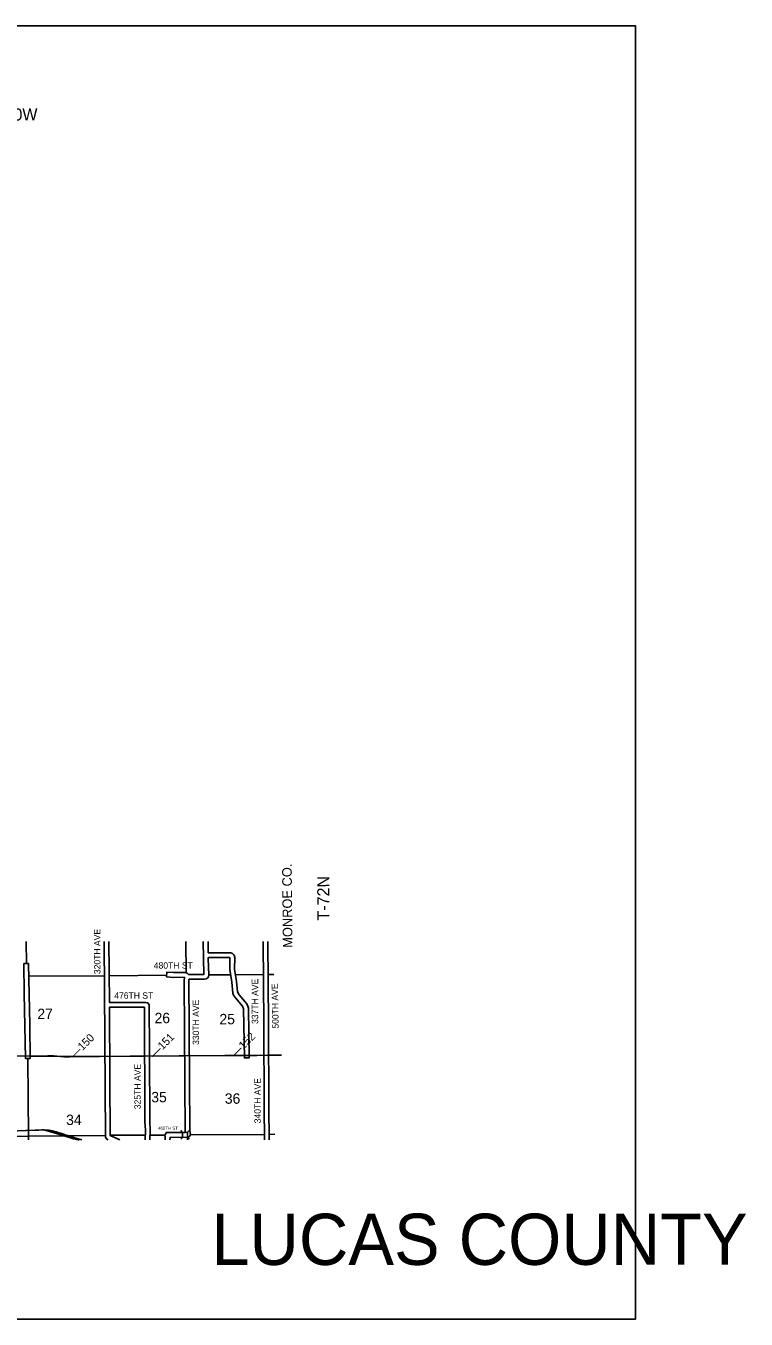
# Model space of a CAD drawing. Extents: x 10133 to 81668, y 5524 to 11018.
# Drawn here: x 19515 to 20640, y 7924 to 9944 of the extents above; entities that cross this region are included whole.
import ezdxf

# ---------------------------------------------------------------- set-up
doc = ezdxf.new("R2010")
doc.units = 0
for name, color, linetype in [('Default', 7, 'Continuous'), ('DsnShtRevisedText', 7, 'Continuous'), ('Level 3', 7, 'Continuous')]:
    doc.layers.add(name, color=color, linetype=linetype)

msp = doc.modelspace()

# ---------------------------------------------------------------- linework, layer by layer
at = {"layer": 'Default'}
for p, q in [((19759.3, 8215.7), (19756.5, 8218.5)), ((19759.4, 8207.9), (19756.6, 8205.1)), ((19767.2, 8215.8), (19769.9, 8218.6)), ((19767.2, 8208), (19770, 8205.2))]:
    msp.add_line(p, q, dxfattribs=at)
for points in [[(19515.1, 8514), (19515.3, 8479.3)], [(19643.2, 8203.9), (19641.9, 8204.5), (19640.1, 8206.1), (19639, 8208.5), (19636.9, 8514)], [(19644.4, 8514), (19645.1, 8418.6), (19701.7, 8418.7), (19704.9, 8417.8), (19707, 8415), (19707.9, 8343), (19708.2, 8232.6), (19708.8, 8219.4), (19708.5, 8203.9)], [(19732.2, 8203.9), (19732.3, 8209.6), (19731.1, 8210.5), (19733, 8213), (19734.4, 8216), (19736.1, 8215.3), (19763.3, 8215.6), (19761.7, 8453), (19762.3, 8457.4), (19762.2, 8458), (19745.3, 8457.7), (19734.5, 8458.5), (19735.1, 8466), (19745.5, 8465.2), (19762.8, 8465.4), (19766.5, 8464.5), (19768.5, 8462.4), (19792.7, 8462.5), (19791.7, 8514)], [(19799.2, 8514), (19799.5, 8496.2), (19834.7, 8496.2), (19837.4, 8495.2), (19839.9, 8492.4), (19840.9, 8488.9), (19840.6, 8470.7), (19843.9, 8451.5), (19845.2, 8435.3), (19848, 8430.5), (19859.5, 8417.2), (19861, 8414.4), (19862.3, 8409.7), (19863.7, 8332.4), (19856.2, 8332.1), (19854.8, 8408.6), (19853.2, 8413.1), (19842.1, 8425.8), (19839.2, 8430.1), (19837.9, 8433.4), (19836.4, 8450.5), (19833.1, 8470.1), (19833.3, 8488.8), (19800.1, 8488.7), (19799.7, 8487.5), (19800.3, 8461.2), (19799.9, 8458.8), (19798.8, 8457), (19796.5, 8455.4), (19793.9, 8455), (19769.4, 8454.8), (19770.6, 8217.9), (19771.8, 8212.5), (19770.6, 8209.7), (19769.1, 8208.6), (19767.2, 8208.1), (19739.8, 8207.9), (19739.7, 8203.9)], [(19764.6, 8514), (19765, 8465.1)], [(19887.5, 8203.9), (19886.8, 8254.7), (19886.5, 8385.6), (19885.3, 8514)], [(19892.8, 8514), (19894, 8385.6), (19894.3, 8254.8), (19895, 8203.9)], [(19511.9, 8432.4), (19511.4, 8479.3), (19518.8, 8479.3), (19520.6, 8383.1), (19521.4, 8331.3), (19513.9, 8331.2), (19511.9, 8432.4)], [(19519.1, 8459.9), (19637.1, 8460.1)], [(19644.6, 8460.2), (19734.7, 8461.3)], [(19800.3, 8461.9), (19834.6, 8462)], [(19842.3, 8462), (19885.7, 8462.1)], [(19893.2, 8462.2), (19901.9, 8462.4)], [(19701, 8203.9), (19701.3, 8219.3), (19700.7, 8232.6), (19699.8, 8411.2), (19664.8, 8411.3), (19645.2, 8411.1), (19645.6, 8298.7), (19646.3, 8210.7), (19661.4, 8203.9)], [(19517.7, 8331.2), (19518.6, 8209.9)], [(19521.4, 8334.9), (19638, 8334.4)], [(19645.5, 8334.4), (19700.4, 8334.8)], [(19707.9, 8334.9), (19762.4, 8335.3)], [(19769.8, 8335.3), (19856.1, 8336)], [(19863.6, 8336), (19886.8, 8336.2)], [(19894.2, 8336.3), (19902.8, 8336.5)], [(19315.5, 8203.9), (19322.2, 8204.5), (19337.6, 8207.5), (19349.6, 8209.5), (19356.3, 8211.1), (19366.4, 8212.7), (19542.4, 8219.6), (19558.6, 8215.1), (19572.8, 8211), (19588.8, 8205.7), (19596.3, 8204.3), (19598, 8203.9)], [(19398.1, 8208.4), (19518.6, 8209.9), (19638.8, 8211.1)], [(19398.1, 8208.4), (19518.6, 8209.9)], [(19514.4, 8218.4), (19530.1, 8219.1), (19534.8, 8219.3), (19539.5, 8219.5), (19541.1, 8219.5), (19542.7, 8219.5), (19544, 8219.4), (19545.4, 8219.4), (19546.9, 8219.3), (19548.3, 8219.2), (19549.7, 8219), (19551, 8218.9), (19552.1, 8218.7), (19553.2, 8218.5), (19554.5, 8218.2), (19555.9, 8218), (19556.9, 8217.8), (19557.9, 8217.5), (19559.2, 8217.2), (19560.5, 8216.8), (19561.8, 8216.5), (19563.5, 8216), (19566, 8215.2), (19568.6, 8214.4), (19573.1, 8213), (19577.6, 8211.5), (19585.2, 8209.2), (19592.7, 8206.8), (19596.4, 8205.6), (19600.2, 8204.4), (19602, 8203.9)], [(19518.6, 8209.9), (19638.8, 8211.1)], [(19518.6, 8209.9), (19518.6, 8203.9)], [(19642.5, 8204.2), (19642.5, 8203.9)], [(19646.3, 8211.2), (19701.1, 8211.4)], [(19646.3, 8211.2), (19701.2, 8211.4)], [(19708.6, 8211.5), (19732.5, 8211.6)], [(19708.7, 8211.5), (19732.5, 8211.6)], [(19767, 8208.1), (19767, 8203.9)], [(19771.7, 8211.8), (19887.4, 8212.6)], [(19771.7, 8211.8), (19887.4, 8212.6)], [(19894.9, 8212.6), (19903.7, 8212.7)]]:
    msp.add_lwpolyline(points, dxfattribs=at)
msp.add_lwpolyline([(19759.3, 8215.7), (19767.2, 8215.8), (19767.2, 8208), (19759.4, 8207.9)], close=True, dxfattribs=at)
at = {"layer": 'DsnShtRevisedText'}
msp.add_lwpolyline([(19914, 8336.1), (19900.5, 8336.2), (19875.6, 8336), (19857.7, 8336), (19825.6, 8335.7), (19754.3, 8335.2), (19677.8, 8334.8), (19629.8, 8334.3), (19583.2, 8333.8), (19573.7, 8333.9), (19557.5, 8335.2), (19549.1, 8335.3), (19492.3, 8334.9)], dxfattribs=at)
at = {"layer": 'Level 3'}
msp.add_lwpolyline([(17332.5, 9944), (20467.5, 9944), (20467.5, 7924), (17332.5, 7924)], close=True, dxfattribs=at)

# ---------------------------------------------------------------- texts
at = {"layer": 'Default'}
for s, height, rotation, p in [('R-20W', 18.75, 0.4163, (19454.8, 9795.9)), ('MONROE CO.', 15, 90.5406, (19931.2, 8504.1)), ('T-72N', 18.75, 90.2756, (19988.9, 8546.7)), ('320TH AVE', 10, 90, (19631.1, 8462.9)), ('337TH AVE', 10, 90, (19877.6, 8385)), ('500TH AVE', 10, 91, (19909.7, 8377.8)), ('27', 16.25, 0.015, (19532.5, 8392.7)), ('330TH AVE', 10, 90, (19785.2, 8352.4)), ('26', 16.25, 0.0158, (19715.7, 8386.2)), ('25', 16.25, 0.0164, (19817.1, 8384.5)), ('‒‒150', 12.5, 45, (19589.8, 8329.4)), ('‒‒151', 12.5, 45, (19714.9, 8330.5)), ('‒‒152', 12.5, 45, (19841.4, 8331.4)), ('325TH AVE', 10, 90, (19694, 8252)), ('340TH AVE', 10, 90, (19881.7, 8229.9)), ('35', 16.25, 0.0158, (19710.6, 8262.7)), ('36', 16.25, 0.0164, (19825.5, 8260.4)), ('34', 16.25, 0.015, (19577.5, 8227.2)), ('LUCAS COUNTY', 80, 0.0203, (19804.5, 8008.6))]:
    msp.add_text(s, height=height, rotation=rotation, dxfattribs=at).set_placement(p)
for s, height, p in [('480TH ST', 10, (19714.5, 8471.5)), ('476TH ST', 10, (19652.7, 8424.4)), ('460TH ST', 5, (19720.9, 8219.7))]:
    msp.add_text(s, height=height, dxfattribs=at).set_placement(p)

doc.saveas('drawing.dxf')
